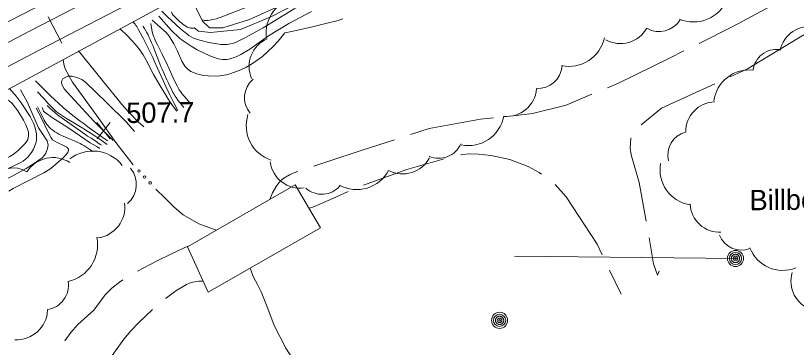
# Model space of a CAD drawing. Extents: x 2361284 to 2366480, y 6976556 to 6985346.
# Drawn here: x 2363998.2 to 2364182.3, y 6978509.3 to 6978587.5 of the extents above; entities that cross this region are included whole.
import ezdxf

# ---------------------------------------------------------------- set-up
doc = ezdxf.new("R2010")
doc.units = 0
doc.header["$LTSCALE"] = 1.9
for name, color, linetype, lineweight in [('11', 7, 'Continuous', 13), ('12', 7, 'Continuous', 13), ('13', 7, 'Continuous', 13), ('15', 7, 'Continuous', 13), ('16', 7, 'Continuous', 13), ('20', 7, 'Continuous', 13), ('21', 7, 'Continuous', 13), ('29', 7, 'Continuous', 13), ('3', 7, 'Continuous', 13), ('4', 7, 'Continuous', 13), ('8', 7, 'Continuous', 13)]:
    doc.layers.add(name, color=color, linetype=linetype, lineweight=lineweight)

msp = doc.modelspace()

# ---------------------------------------------------------------- linework, layer by layer
at = {"layer": '11'}
msp.add_line((2364115.874, 6978530.795), (2364168.462, 6978530.275), dxfattribs=at)
at = {"layer": '12'}
for p, q in [((2364020.521, 6978558.447), (2364017.404, 6978562.298)), ((2364017.441, 6978558.418), (2364020.484, 6978562.327))]:
    msp.add_line(p, q, dxfattribs=at)
for points in [[(2364032.021, 6978587.366), (2364034.943, 6978584.053), (2364036.901, 6978582.181), (2364037.77, 6978581.5), (2364039.609, 6978580.277), (2364041.028, 6978579.45), (2364043.991, 6978578.028), (2364045.984, 6978577.311), (2364047.007, 6978577.121), (2364048.012, 6978577.112), (2364048.498, 6978577.191), (2364050.21, 6978577.757), (2364051.325, 6978578.289), (2364053.466, 6978579.588), (2364057.817, 6978582.72), (2364062.68, 6978585.617), (2364068.023, 6978588.458)], [(2364022.9, 6978584.249), (2364023.382, 6978583.854), (2364023.615, 6978583.652), (2364023.957, 6978583.342), (2364024.453, 6978582.853), (2364025.687, 6978581.553), (2364026.286, 6978580.892), (2364026.864, 6978580.215), (2364027.142, 6978579.869), (2364027.675, 6978579.159), (2364027.928, 6978578.793), (2364028.287, 6978578.229), (2364028.606, 6978577.684), (2364029.209, 6978576.578), (2364030.367, 6978574.345), (2364030.767, 6978573.609), (2364030.975, 6978573.245), (2364032.524, 6978570.577), (2364033.313, 6978569.252), (2364034.125, 6978567.939), (2364034.543, 6978567.289), (2364035.077, 6978566.51), (2364035.448, 6978566.001), (2364036.205, 6978564.994)], [(2363999.354, 6978570.014), (2364000.971, 6978567.2), (2364003.609, 6978561.063), (2364005.649, 6978557.973), (2364005.84, 6978557.382), (2364005.879, 6978556.96), (2364005.766, 6978556.134), (2364005.354, 6978555.076), (2364005.056, 6978554.589), (2364004.457, 6978553.971), (2364002.212, 6978552.407), (2364000.697, 6978551.474), (2363997.587, 6978549.766), (2363995.318, 6978548.604)], [(2364003.409, 6978569.493), (2364003.936, 6978568.962), (2364004.279, 6978568.598), (2364004.953, 6978567.857), (2364005.847, 6978566.864), (2364006.301, 6978566.375), (2364006.766, 6978565.897), (2364007.004, 6978565.664), (2364007.493, 6978565.212), (2364007.746, 6978564.993), (2364008.135, 6978564.678), (2364008.812, 6978564.176), (2364009.274, 6978563.857), (2364010.215, 6978563.249), (2364011.174, 6978562.669), (2364013.111, 6978561.537), (2364014.071, 6978560.957), (2364014.545, 6978560.657), (2364016.916, 6978559.131), (2364018.091, 6978558.351), (2364019.253, 6978557.539), (2364019.828, 6978557.117)]]:
    msp.add_lwpolyline(points, dxfattribs=at)
at = {"layer": '13'}
for points in [[(2364042.263, 6978586.203), (2364043.908, 6978584.609), (2364047.058, 6978584.569), (2364053.349, 6978586.588), (2364060.968, 6978589.991), (2364067.641, 6978593.895), (2364073.966, 6978596.585), (2364085.53, 6978602.525), (2364100.286, 6978610.396), (2364109.839, 6978615.367), (2364122.301, 6978621.526), (2364134.064, 6978627.578), (2364142.174, 6978631.826), (2364160.898, 6978639.943), (2364175.49, 6978647.282)], [(2364040.349, 6978584.585), (2364041.366, 6978583.823), (2364044.159, 6978583.48), (2364051.251, 6978584.218), (2364058.424, 6978587.217), (2364064.973, 6978590.539), (2364070.255, 6978593.529), (2364077.415, 6978596.588), (2364087.737, 6978601.836), (2364093.655, 6978605.152), (2364106.768, 6978611.257), (2364120.233, 6978618.106), (2364131.446, 6978624.173), (2364138.156, 6978627.337)], [(2364042.12, 6978586.492), (2364042.517, 6978586.389), (2364042.717, 6978586.352), (2364043.017, 6978586.319), (2364043.314, 6978586.32), (2364043.462, 6978586.334), (2364044.061, 6978586.424), (2364044.361, 6978586.477), (2364044.811, 6978586.568), (2364045.481, 6978586.732), (2364046.141, 6978586.936), (2364046.465, 6978587.053), (2364053.15, 6978589.647), (2364055.774, 6978590.626), (2364058.109, 6978591.489), (2364059.274, 6978591.929), (2364061.013, 6978592.612), (2364062.166, 6978593.095), (2364062.928, 6978593.431), (2364064.439, 6978594.132), (2364065.189, 6978594.495), (2364066.681, 6978595.239), (2364071.127, 6978597.528)], [(2364032.68, 6978588.512), (2364034.074, 6978587.165), (2364037.009, 6978584.455), (2364038.562, 6978583.147), (2364039.075, 6978582.773), (2364040.179, 6978582.175), (2364041.358, 6978581.735), (2364043.802, 6978581.126), (2364046.605, 6978580.685), (2364048.02, 6978580.686), (2364049.387, 6978580.93), (2364050.04, 6978581.166), (2364052.289, 6978582.224), (2364056.629, 6978584.62), (2364063.897, 6978589.069), (2364067.494, 6978590.875), (2364069.956, 6978591.928), (2364075.022, 6978593.745)], [(2364040.349, 6978584.585), (2364040.167, 6978584.543), (2364040.045, 6978584.524), (2364039.802, 6978584.51), (2364039.681, 6978584.514), (2364039.438, 6978584.542), (2364039.195, 6978584.597), (2364039.033, 6978584.647), (2364038.709, 6978584.778), (2364038.346, 6978584.97), (2364038.104, 6978585.121), (2364037.942, 6978585.231), (2364037.621, 6978585.471), (2364037.38, 6978585.666), (2364036.899, 6978586.089), (2364036.42, 6978586.543), (2364035.471, 6978587.488), (2364035.383, 6978587.582), (2364035.241, 6978587.771), (2364035.133, 6978587.962), (2364034.962, 6978588.364)], [(2364025.853, 6978586.007), (2364025.936, 6978585.942), (2364026.104, 6978585.786), (2364026.272, 6978585.597), (2364026.384, 6978585.454), (2364026.609, 6978585.137), (2364026.777, 6978584.875), (2364027.11, 6978584.305), (2364028.067, 6978582.527), (2364028.368, 6978581.977), (2364028.947, 6978580.88), (2364029.501, 6978579.783), (2364029.86, 6978579.049), (2364030.564, 6978577.57), (2364030.919, 6978576.803), (2364031.613, 6978575.262), (2364032.989, 6978572.174), (2364033.7, 6978570.641), (2364034.601, 6978568.795), (2364035.219, 6978567.573), (2364035.639, 6978566.762), (2364036.493, 6978565.147)], [(2364028.193, 6978585.029), (2364028.453, 6978584.68), (2364028.624, 6978584.425), (2364028.96, 6978583.87), (2364029.124, 6978583.574), (2364029.443, 6978582.955), (2364029.747, 6978582.315), (2364029.94, 6978581.885), (2364030.301, 6978581.038), (2364030.552, 6978580.421), (2364031.037, 6978579.186), (2364031.994, 6978576.717), (2364032.494, 6978575.49), (2364032.762, 6978574.859), (2364033.315, 6978573.605), (2364033.887, 6978572.36), (2364034.277, 6978571.533), (2364035.078, 6978569.884), (2364035.33, 6978569.396), (2364035.508, 6978569.079), (2364035.884, 6978568.462), (2364036.083, 6978568.161), (2364036.502, 6978567.569), (2364036.949, 6978566.988), (2364037.263, 6978566.605), (2364037.927, 6978565.841)], [(2364030.097, 6978585.597), (2364030.363, 6978584.108), (2364030.526, 6978583.37), (2364030.662, 6978582.886), (2364030.742, 6978582.647), (2364030.879, 6978582.294), (2364031.131, 6978581.718), (2364031.306, 6978581.338), (2364031.668, 6978580.587), (2364032.803, 6978578.364), (2364033.357, 6978577.247), (2364033.713, 6978576.492), (2364034.405, 6978574.973), (2364035.324, 6978572.943), (2364035.797, 6978571.935), (2364036.288, 6978570.934), (2364036.543, 6978570.438), (2364036.81, 6978569.976), (2364037.006, 6978569.679), (2364037.144, 6978569.487), (2364037.433, 6978569.11), (2364037.891, 6978568.561), (2364038.52, 6978567.841), (2364038.831, 6978567.478), (2364039.279, 6978566.923), (2364039.489, 6978566.636)], [(2364030.41, 6978586.42), (2364033.688, 6978583.47), (2364034.394, 6978582.658), (2364035.544, 6978580.818), (2364036.411, 6978579.1), (2364037.447, 6978576.725), (2364038.144, 6978575.593), (2364038.944, 6978574.767), (2364039.57, 6978574.344), (2364040.982, 6978573.75), (2364042.563, 6978573.387), (2364043.62, 6978573.26), (2364045.727, 6978573.245), (2364047.912, 6978573.52), (2364049, 6978573.816), (2364051.368, 6978574.73), (2364052.493, 6978575.262), (2364054.117, 6978576.171), (2364056.433, 6978577.826), (2364058.985, 6978580.165), (2364060.131, 6978581.418), (2364061.72, 6978583.437)], [(2364028.488, 6978561.29), (2364027.635, 6978562.005), (2364027.221, 6978562.374), (2364026.819, 6978562.756), (2364026.623, 6978562.953), (2364025.455, 6978564.163), (2364024.879, 6978564.775), (2364024.031, 6978565.704), (2364023.205, 6978566.653), (2364022.803, 6978567.137), (2364018.951, 6978571.868), (2364017.036, 6978574.243), (2364013.069, 6978579.194)], [(2364002.904, 6978572.138), (2364003.612, 6978571.419), (2364005.045, 6978569.998), (2364006.562, 6978568.51), (2364007.327, 6978567.772), (2364008.49, 6978566.683), (2364009.281, 6978565.973), (2364009.681, 6978565.624), (2364010.291, 6978565.108), (2364011.324, 6978564.268), (2364012.021, 6978563.72), (2364013.43, 6978562.646), (2364014.142, 6978562.119), (2364015.575, 6978561.078), (2364019.909, 6978557.998)], [(2364026.279, 6978560.149), (2364024.358, 6978562.382), (2364019.563, 6978567.096), (2364014.82, 6978571.731), (2364013.831, 6978572.43), (2364013.078, 6978572.764), (2364011.545, 6978573.19), (2364010.539, 6978573.176), (2364010.032, 6978573.01), (2364009.371, 6978572.55), (2364009.108, 6978572.139), (2364009.045, 6978571.846), (2364009.142, 6978571.224), (2364009.695, 6978570.253), (2364011.269, 6978568.488), (2364016.706, 6978562.599), (2364021.249, 6978558.021)], [(2363996.821, 6978570.32), (2363998.369, 6978568.485), (2363999.542, 6978566.934), (2364001.694, 6978563.686), (2364002.557, 6978561.98), (2364002.87, 6978561.061), (2364003.151, 6978559.66), (2364003.163, 6978558.29), (2364003.052, 6978557.638), (2364002.43, 6978555.989), (2364001.962, 6978555.192), (2364001.088, 6978554.099), (2364000.038, 6978553.203), (2363999.457, 6978552.854), (2363994.808, 6978550.639)], [(2363996.547, 6978567.568), (2363997.391, 6978566.795), (2363998.751, 6978565.048), (2364000.088, 6978562.87), (2364000.63, 6978561.766), (2364001.229, 6978560.091), (2364001.289, 6978559.174), (2364001.069, 6978558.33), (2364000.869, 6978557.92), (2364000.465, 6978557.343), (2363998.814, 6978555.675), (2363997.66, 6978554.786), (2363996.857, 6978554.27), (2363995.152, 6978553.373), (2363986.112, 6978549.176), (2363976.892, 6978544.86), (2363974.034, 6978543.683), (2363970.157, 6978542.27), (2363968.244, 6978541.497), (2363964.045, 6978539.583), (2363961.282, 6978538.232), (2363955.842, 6978535.348)], [(2364005.69, 6978566.274), (2364006.46, 6978565.532), (2364006.85, 6978565.167), (2364007.446, 6978564.636), (2364008.064, 6978564.13), (2364008.383, 6978563.89), (2364010.506, 6978562.37), (2364014.787, 6978559.39), (2364015.191, 6978559.115), (2364016.01, 6978558.582), (2364017.106, 6978557.878), (2364017.649, 6978557.514), (2364018.186, 6978557.133), (2364018.45, 6978556.934)], [(2364003.076, 6978565.669), (2364004.295, 6978563.351), (2364005.801, 6978560.201), (2364006.582, 6978558.682), (2364006.932, 6978558.243), (2364008.012, 6978557.556), (2364009.654, 6978556.828), (2364010.295, 6978556.45), (2364010.659, 6978556.009), (2364010.7, 6978555.751), (2364010.509, 6978555.199), (2364010.24, 6978554.799), (2364009.556, 6978554.06), (2364006.546, 6978551.476), (2364004.911, 6978550.405), (2363997.665, 6978546.777), (2363996.591, 6978546.117)], [(2364003.422, 6978566.023), (2364003.802, 6978565.217), (2364004.302, 6978564.141), (2364004.561, 6978563.606), (2364004.975, 6978562.812), (2364005.197, 6978562.42), (2364005.427, 6978562.058), (2364005.593, 6978561.829), (2364005.708, 6978561.682), (2364005.95, 6978561.4), (2364006.142, 6978561.199), (2364006.548, 6978560.82), (2364006.983, 6978560.472), (2364007.287, 6978560.254), (2364007.495, 6978560.116), (2364007.925, 6978559.851), (2364008.427, 6978559.572), (2364008.77, 6978559.396), (2364009.475, 6978559.061), (2364010.563, 6978558.59), (2364012.033, 6978557.977), (2364012.76, 6978557.66), (2364013.471, 6978557.325), (2364013.818, 6978557.148), (2364014.327, 6978556.869), (2364014.817, 6978556.57), (2364015.055, 6978556.412), (2364015.978, 6978555.779), (2364016.434, 6978555.455)], [(2364004.494, 6978565.803), (2364004.633, 6978565.455), (2364004.808, 6978564.989), (2364004.964, 6978564.807), (2364006.958, 6978563.393), (2364009.69, 6978561.661), (2364011.043, 6978560.774), (2364015.785, 6978557.529), (2364016.526, 6978557.113), (2364017.529, 6978556.571), (2364017.987, 6978556.2)]]:
    msp.add_lwpolyline(points, dxfattribs=at)
at = {"layer": '15'}
msp.add_line((2364138.275, 6978527.542), (2364141, 6978521.849), dxfattribs=at)
for points in [[(2364177.133, 6978590.145), (2364167.322, 6978584.922), (2364159.379, 6978580.935)], [(2364166.714, 6978573.046), (2364170.827, 6978574.905), (2364184.072, 6978582.94)], [(2364155.806, 6978579.141), (2364152.432, 6978577.45), (2364140.387, 6978571.585), (2364137.777, 6978570.49)], [(2364145.732, 6978561.736), (2364150.524, 6978565.711), (2364163.07, 6978571.391)], [(2364134.091, 6978568.945), (2364128.036, 6978566.398), (2364120.124, 6978564.382), (2364114.889, 6978563.823)], [(2364110.913, 6978563.405), (2364107.836, 6978563.075), (2364095.766, 6978560.89), (2364091.35, 6978559.467)], [(2364087.541, 6978558.251), (2364079.974, 6978555.789), (2364071.829, 6978553.112), (2364068.54, 6978552.01)], [(2364146.887, 6978539.085), (2364145.291, 6978548.141), (2364143.388, 6978554.662), (2364143.132, 6978556.27), (2364143.31, 6978558.591), (2364143.33, 6978558.642)], [(2364080.292, 6978547.553), (2364090.448, 6978551.209), (2364099.305, 6978553.703)], [(2364103.175, 6978554.7), (2364103.445, 6978554.752), (2364105.394, 6978554.881), (2364107.335, 6978554.819), (2364110.317, 6978554.528), (2364114.727, 6978553.579), (2364119.073, 6978551.931), (2364121.686, 6978550.546), (2364122.26, 6978550.121)], [(2364064.741, 6978550.744), (2364063.705, 6978550.394), (2364062.768, 6978550.005), (2364061.466, 6978549.203), (2364060.871, 6978548.688), (2364060.326, 6978548.113), (2364059.625, 6978547.186), (2364058.809, 6978545.718), (2364058.154, 6978544.172)], [(2364067.414, 6978542.1), (2364068.062, 6978542.306), (2364068.71, 6978542.542), (2364073.858, 6978544.792), (2364076.606, 6978546.018)], [(2364125.424, 6978547.692), (2364128.052, 6978544.807), (2364135.337, 6978533.655), (2364136.541, 6978531.146)], [(2364150, 6978527.254), (2364149.598, 6978526.37), (2364148.663, 6978529.001), (2364147.584, 6978535.141)], [(2364026.952, 6978527.294), (2364026.991, 6978527.314), (2364031.45, 6978529.597), (2364035.144, 6978531.402), (2364038.868, 6978533.127)], [(2364016.64, 6978518.096), (2364019.365, 6978521.691), (2364020.919, 6978523.306), (2364022.686, 6978524.713), (2364023.531, 6978525.221)], [(2364042.446, 6978524.921), (2364041.466, 6978524.912), (2364039.988, 6978524.678), (2364039.25, 6978524.461), (2364038.533, 6978524.144), (2364036.027, 6978522.68), (2364033.772, 6978520.988), (2364033.583, 6978520.828)], [(2364016.64, 6978518.096), (2364012.872, 6978514.699), (2364011.278, 6978512.854), (2364009.817, 6978510.84)], [(2364030.528, 6978518.248), (2364030.438, 6978518.178), (2364027.277, 6978515.196)], [(2364027.277, 6978515.196), (2364025.465, 6978513.289), (2364023.774, 6978511.283), (2364020.98, 6978507.446)]]:
    msp.add_lwpolyline(points, dxfattribs=at)
at = {"layer": '16'}
for centre, radius, start, end in [((2364065.851, 6978583.383), 8.546, 98.1192, 188.1192), ((2364158.072, 6978594.518), 8.546, 247.21802, 337.21802), ((2364149.985, 6978589.389), 5.694, 239.47537, 329.47537), ((2364185.357, 6978577.926), 6.973, 78.85897, 168.85897), ((2364140.82, 6978588.011), 7.125, 240.94681, 330.94681), ((2364060.398, 6978575.485), 7.125, 113.41298, 203.41298), ((2364128.709, 6978584.052), 8.546, 257.98776, 347.98776), ((2364177.642, 6978573.938), 5.573, 82.76813, 172.76813), ((2364121.378, 6978575.999), 5.694, 266.31707, 356.31707), ((2364171.17, 6978566.316), 8.364, 82.76813, 172.76813), ((2364057.888, 6978568.16), 5.694, 130.32552, 220.32552), ((2364113.958, 6978570.837), 7.125, 265.07212, 355.07212), ((2364163.216, 6978560.174), 6.973, 91.17969, 181.17969), ((2364061.147, 6978561.543), 8.546, 162.00709, 252.00709), ((2364104.942, 6978565.39), 8.546, 259.00259, 349.00259), ((2364157.573, 6978554.64), 5.573, 104.40169, 194.40169), ((2364097.972, 6978559.559), 5.694, 246.59057, 336.59057), ((2364016.435, 6978546.766), 8.805, 38.04786, 128.04786), ((2364007.046, 6978546.698), 7.341, 57.0717, 147.0717), ((2364089.48, 6978557.293), 7.125, 242.48715, 332.48715), ((2363997.68, 6978545.742), 5.867, 57.17851, 147.17851), ((2364020.836, 6978547.717), 5.867, 310.28619, 40.28619), ((2364065.315, 6978553.951), 7.125, 187.69862, 277.69862), ((2364158.528, 6978551.179), 8.364, 170.05462, 260.05462), ((2364078.666, 6978555.053), 8.546, 241.59318, 331.59318), ((2364070.403, 6978551.091), 5.694, 228.87363, 318.87363), ((2364016.643, 6978542.388), 7.341, 277.37385, 7.37385), ((2364164.246, 6978543.412), 6.973, 182.44866, 272.44866), ((2364008.741, 6978533.468), 8.805, 281.79642, 11.79642), ((2364169.341, 6978537.833), 5.573, 201.48479, 291.48479), ((2364179.135, 6978535.819), 8.364, 201.48479, 291.48479), ((2364188.013, 6978524.875), 6.973, 162.60493, 252.60493), ((2364004.826, 6978524.024), 5.867, 278.38109, 8.38109), ((2363998.449, 6978518.46), 7.341, 267.11131, 357.11131)]:
    msp.add_arc(centre, radius, start, end, dxfattribs=at)
at = {"layer": '20'}
msp.add_lwpolyline([(2364061.75, 6978583.427), (2364063.278, 6978583.742), (2364064.795, 6978584.067), (2364068.237, 6978584.85), (2364071.67, 6978585.663), (2364074.243, 6978586.337), (2364075.359, 6978586.698)], dxfattribs=at)
at = {"layer": '21'}
for points in [[(2364009.477, 6978577.15), (2364009.628, 6978576.012), (2364009.743, 6978575.453), (2364009.948, 6978574.915), (2364011.668, 6978571.781), (2364017.83, 6978563.25), (2364021.873, 6978557.607), (2364025.973, 6978552.356)], [(2364031.318, 6978546.627), (2364033.378, 6978544.517), (2364035.58, 6978542.347), (2364037.767, 6978540.548), (2364041.437, 6978538.442), (2364045.492, 6978536.92)], [(2364053.547, 6978527.957), (2364053.927, 6978526.89), (2364054.347, 6978525.834), (2364055.223, 6978524.122), (2364056.109, 6978522.421), (2364057.678, 6978518.466), (2364059.206, 6978514.49), (2364061.927, 6978509.145), (2364065.245, 6978504.057)]]:
    msp.add_lwpolyline(points, dxfattribs=at)
for centre in [(2364027.31, 6978550.865), (2364028.607, 6978549.449), (2364029.938, 6978548.065)]:
    msp.add_circle(centre, 0.3, dxfattribs=at)
at = {"layer": '29'}
msp.add_line((2364005.931, 6978587.208), (2364009.14, 6978580.997), dxfattribs=at)
for points in [[(2363926.674, 6978544.462), (2363964.107, 6978564.229), (2364001.623, 6978583.856), (2364042.853, 6978605.198), (2364084.062, 6978626.542), (2364128.694, 6978649.718), (2364173.346, 6978672.904), (2364214.057, 6978694.031), (2364254.768, 6978715.12), (2364294.894, 6978735.833), (2364335.019, 6978756.535), (2364356.186, 6978767.468), (2364377.374, 6978778.399), (2364394.91, 6978787.357), (2364412.486, 6978796.234)], [(2363929.006, 6978540.034), (2363966.429, 6978559.8), (2364003.925, 6978579.417), (2364045.145, 6978600.751), (2364086.354, 6978622.094), (2364130.996, 6978645.279), (2364175.648, 6978668.465), (2364216.349, 6978689.584), (2364257.061, 6978710.672), (2364297.185, 6978731.384), (2364337.311, 6978752.087), (2364358.478, 6978763.02), (2364379.656, 6978773.951), (2364397.172, 6978782.897), (2364414.739, 6978791.766)]]:
    msp.add_lwpolyline(points, dxfattribs=at)
at = {"layer": '3'}
msp.add_lwpolyline([(2364070.138, 6978537.455), (2364064.171, 6978547.62), (2364038.719, 6978533.036), (2364043.651, 6978522.302)], close=True, dxfattribs=at)
at = {"layer": '4'}
for centre, radius in [((2364167.962, 6978530.275), 1.9), ((2364167.962, 6978530.275), 1.442), ((2364167.962, 6978530.275), 0.539), ((2364167.962, 6978530.275), 0.192), ((2364112.337, 6978515.695), 1.9), ((2364112.337, 6978515.695), 1.442), ((2364112.337, 6978515.695), 0.539), ((2364112.337, 6978515.695), 0.192)]:
    msp.add_circle(centre, radius, dxfattribs=at)
for centre, start, end in [((2364167.962, 6978530.275), 95.96582, 107.21585), ((2364167.962, 6978530.275), 84.71553, 95.96557), ((2364167.962, 6978530.275), 73.46552, 84.71555), ((2364167.962, 6978530.275), 174.71552, 185.96556), ((2364167.962, 6978530.275), 163.46611, 174.71615), ((2364167.962, 6978530.275), 185.96287, 197.21291), ((2364167.962, 6978530.275), 152.21535, 163.46538), ((2364167.962, 6978530.275), 197.21479, 208.46483), ((2364167.962, 6978530.275), 140.96646, 152.21649), ((2364167.962, 6978530.275), 208.46822, 219.71826), ((2364167.962, 6978530.275), 129.71376, 140.96379), ((2364167.962, 6978530.275), 219.71376, 230.96379), ((2364167.962, 6978530.275), 118.46406, 129.71409), ((2364167.962, 6978530.275), 230.96397, 242.214), ((2364167.962, 6978530.275), 107.21593, 118.46597), ((2364167.962, 6978530.275), 242.21812, 253.46815), ((2364167.962, 6978530.275), 62.21535, 73.46538), ((2364167.962, 6978530.275), 287.21593, 298.46597), ((2364167.962, 6978530.275), 50.96397, 62.214), ((2364167.962, 6978530.275), 298.46406, 309.71409), ((2364167.962, 6978530.275), 39.71588, 50.96591), ((2364167.962, 6978530.275), 309.71589, 320.96592), ((2364167.962, 6978530.275), 28.46656, 39.7166), ((2364167.962, 6978530.275), 320.96646, 332.21649), ((2364167.962, 6978530.275), 17.21479, 28.46483), ((2364167.962, 6978530.275), 332.21419, 343.46422), ((2364167.962, 6978530.275), 5.96345, 17.21348), ((2364167.962, 6978530.275), 343.46611, 354.71615), ((2364167.962, 6978530.275), 354.71553, 5.96557), ((2364167.962, 6978530.275), 253.46258, 264.71261), ((2364167.962, 6978530.275), 264.71553, 275.96557), ((2364167.962, 6978530.275), 275.96582, 287.21585), ((2364112.337, 6978515.695), 118.46406, 129.71409), ((2364112.337, 6978515.695), 107.21593, 118.46597), ((2364112.337, 6978515.695), 95.96582, 107.21585), ((2364112.337, 6978515.695), 84.71553, 95.96557), ((2364112.337, 6978515.695), 73.46552, 84.71555), ((2364112.337, 6978515.695), 62.21535, 73.46538), ((2364112.337, 6978515.695), 50.96397, 62.214), ((2364112.337, 6978515.695), 174.71552, 185.96556), ((2364112.337, 6978515.695), 163.46611, 174.71615), ((2364112.337, 6978515.695), 185.96287, 197.21291), ((2364112.337, 6978515.695), 152.21535, 163.46538), ((2364112.337, 6978515.695), 197.21479, 208.46483), ((2364112.337, 6978515.695), 140.96646, 152.21649), ((2364112.337, 6978515.695), 208.46822, 219.71826), ((2364112.337, 6978515.695), 129.71376, 140.96379), ((2364112.337, 6978515.695), 219.71376, 230.96379), ((2364112.337, 6978515.695), 230.96397, 242.214), ((2364112.337, 6978515.695), 242.21812, 253.46815), ((2364112.337, 6978515.695), 253.46258, 264.71261), ((2364112.337, 6978515.695), 264.71553, 275.96557), ((2364112.337, 6978515.695), 275.96582, 287.21585), ((2364112.337, 6978515.695), 287.21593, 298.46597), ((2364112.337, 6978515.695), 298.46406, 309.71409), ((2364112.337, 6978515.695), 39.71588, 50.96591), ((2364112.337, 6978515.695), 309.71589, 320.96592), ((2364112.337, 6978515.695), 28.46656, 39.7166), ((2364112.337, 6978515.695), 320.96646, 332.21649), ((2364112.337, 6978515.695), 17.21479, 28.46483), ((2364112.337, 6978515.695), 332.21419, 343.46422), ((2364112.337, 6978515.695), 5.96345, 17.21348), ((2364112.337, 6978515.695), 343.46611, 354.71615), ((2364112.337, 6978515.695), 354.71553, 5.96557)]:
    msp.add_arc(centre, 0.973, start, end, dxfattribs=at)
at = {"layer": '8'}
for points in [[(2363970.95, 6978579.764), (2363982.706, 6978585.567), (2363985.464, 6978580.452), (2364032.964, 6978604.875), (2364030.222, 6978608.28), (2364034.17, 6978610.647)], [(2364042.263, 6978586.203), (2364038.888, 6978593.051), (2363992.026, 6978567.725), (2363995.657, 6978561.238)]]:
    msp.add_lwpolyline(points, dxfattribs=at)

# ---------------------------------------------------------------- texts
at = {"layer": '11'}
msp.add_text('Billboard', height=4.799, rotation=0.545, dxfattribs=at).set_placement((2364171.294, 6978541.608))
at = {"layer": '12'}
msp.add_text('507.7', height=4.799, rotation=0.545, dxfattribs=at).set_placement((2364024.33, 6978562.171))

doc.saveas('drawing.dxf')
